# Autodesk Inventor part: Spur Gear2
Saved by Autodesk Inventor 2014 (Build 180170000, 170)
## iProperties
Created: 2015-07
Part Number: Spur Gear2
Material: Steel
Document SubType Name: Modeling
Designer: Brad Factor
Categories: <?xml version="1.0" encoding="UTF-16"?> <MemberInstance><Categories><FamilyTemplate><FamilyTemplateParameter ValueType="xs:double" Id="1" ObjectReferenceKey="da
Density: 1 g/cm^3
Appearance: Steel
CustomPartVersion: 1
Author: Brad Factor
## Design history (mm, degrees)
sketch "Sketch1"
  geometry: C1 r 77.162 at (0, 0)
  constraints: 1 centre point
  dimensions: "d0" = 154.32478 diameter of C1 (= da_da)
extrude "Extrusion1" new body sketch "Sketch1" distance "d1" = 6.35 (= da_b); taper "d2" = 0 deg
sketch "Sketch2"
  geometry: C1 r 77.162 at (0, 0) reference; C2 r 76.36 at (0, 0)
  constraints: 1 centre point, 1 coincident
  dimensions: "d3" = 152.72017 diameter of C2 (= da_dw)
feature "Pitch Diameter" sketch "Sketch2" dims "d4" = 76.2, "d5" = 0
workplane "Work Plane1"
workplane "Work Plane2"
workplane "Work Plane3"
feature "Spur Gear" dims "da_b" = 6.35, "da_d" = 152.4, "da_aw" = 84.1375, "da_da" = 154.32478, "da_df" = 147.97756, "da_dw" = 152.72017, angle "da_beta" = 0 deg, "da_lefttooth" = 0, "da_righttooth" = 0
body "Solid1"
body "Srf1"
other parameters: "d6" = 0, "d7" = 0.29089 (computed from da_z), "d9" = 0, "d14" = 0, "d15" = 84.1375 (= da_aw), "d16" = 0, "d17" = 0, "d18" = 0, "d19" = 84.1375 (= da_aw)
